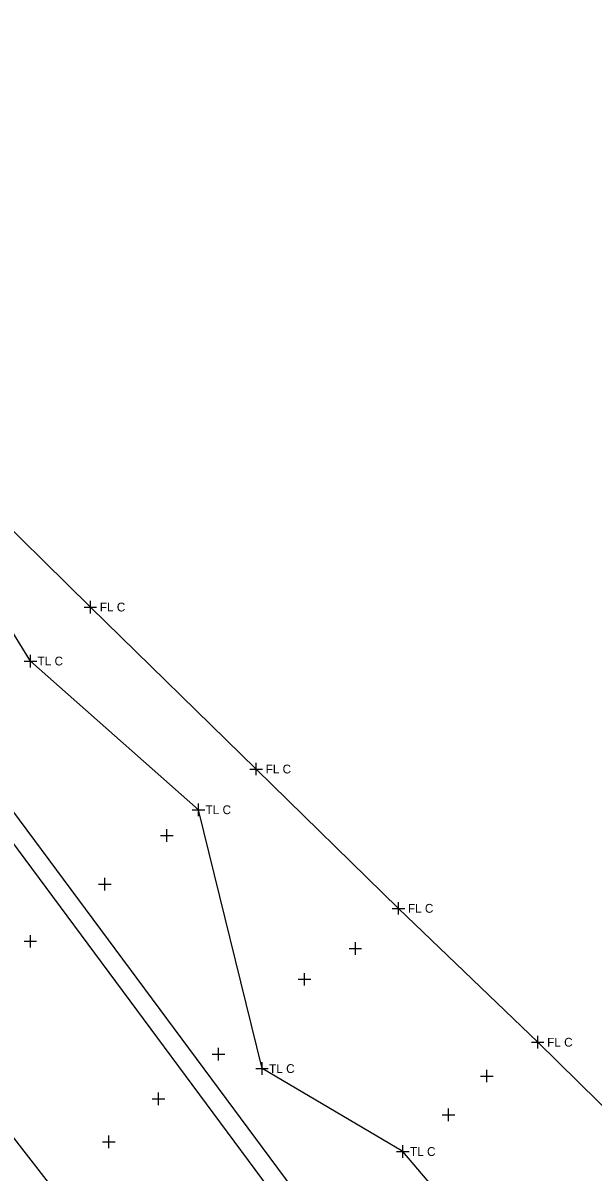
# Model space of a CAD drawing. Extents: x 1324236 to 1326110, y 459090 to 460782.
# Drawn here: x 1325707.2 to 1325797.9, y 459875.9 to 460058.5 of the extents above; entities that cross this region are included whole.
import ezdxf

# ---------------------------------------------------------------- set-up
doc = ezdxf.new("R2010")
doc.units = 0
for name, color, linetype in [('PM_X_CL_Double_Solid', 7, 'Continuous'), ('PV_X_Shoulder_Aggregate', 7, 'Continuous'), ('RD_X_GR_Lt', 7, 'Continuous'), ('RW_X_CL', 7, 'Continuous'), ('RW_X_Esmt_SH', 7, 'Continuous'), ('VG_X_Flower_Bed', 7, 'Continuous')]:
    doc.layers.add(name, color=color, linetype=linetype)

msp = doc.modelspace()

# ---------------------------------------------------------------- linework, layer by layer
at = {"layer": 'PM_X_CL_Double_Solid'}
for p, q in [((1325696.04, 459987.2), (1325717.94, 459965.66)), ((1325717.94, 459965.66), (1325744.3, 459939.92)), ((1325744.3, 459939.92), (1325766.92, 459917.78)), ((1325766.92, 459917.78), (1325789.06, 459896.5)), ((1325789.06, 459896.5), (1325812.12, 459873.88))]:
    msp.add_line(p, q, dxfattribs=at)
at = {"layer": 'PV_X_Shoulder_Aggregate'}
msp.add_lwpolyline([(1325606.5, 460003.97), (1325627.86, 459979.71), (1325648.47, 459953.75), (1325670.82, 459926.9), (1325690.92, 459900.29), (1325711.62, 459873.72), (1325733.33, 459849.01), (1325756.75, 459825.62), (1325779.78, 459800.49), (1325802.43, 459775.88), (1325825.37, 459750.4), (1325848.07, 459724.61), (1325869.88, 459700.51), (1325892.16, 459676.27), (1325913.97, 459651.72)], dxfattribs=at)
at = {"layer": 'RD_X_GR_Lt'}
for p, q in [((1325708.41, 459957.08), (1325689.63, 459987.5)), ((1325735.13, 459933.45), (1325708.41, 459957.08)), ((1325745.23, 459892.31), (1325735.13, 459933.45)), ((1325767.63, 459879.13), (1325745.23, 459892.31)), ((1325789.25, 459853.71), (1325767.63, 459879.13))]:
    msp.add_line(p, q, dxfattribs=at)
at = {"layer": 'RW_X_CL'}
for p, q in [((1325729.11, 459929.37), (1325731.11, 459929.37)), ((1325730.11, 459928.37), (1325730.11, 459930.37)), ((1325720.23, 459920.61), (1325720.23, 459922.61)), ((1325719.23, 459921.61), (1325721.23, 459921.61)), ((1325708.4, 459911.54), (1325708.4, 459913.54)), ((1325707.4, 459912.54), (1325709.4, 459912.54)), ((1325759.07, 459911.4), (1325761.07, 459911.4)), ((1325760.07, 459910.4), (1325760.07, 459912.4)), ((1325751.99, 459905.5), (1325751.99, 459907.5)), ((1325750.99, 459906.5), (1325752.99, 459906.5)), ((1325738.33, 459893.6), (1325738.33, 459895.6)), ((1325737.33, 459894.6), (1325739.33, 459894.6)), ((1325779.99, 459891.13), (1325781.99, 459891.13)), ((1325780.99, 459890.13), (1325780.99, 459892.13)), ((1325727.77, 459887.52), (1325729.77, 459887.52)), ((1325728.77, 459886.52), (1325728.77, 459888.52)), ((1325774.86, 459883.95), (1325774.86, 459885.95)), ((1325773.86, 459884.95), (1325775.86, 459884.95)), ((1325719.86, 459880.69), (1325721.86, 459880.69)), ((1325720.86, 459879.69), (1325720.86, 459881.69))]:
    msp.add_line(p, q, dxfattribs=at)
at = {"layer": 'RW_X_Esmt_SH'}
for p, q in [((1325717.94, 459964.66), (1325717.94, 459966.66)), ((1325716.94, 459965.66), (1325718.94, 459965.66)), ((1325707.41, 459957.08), (1325709.41, 459957.08)), ((1325708.41, 459956.08), (1325708.41, 459958.08)), ((1325744.3, 459938.92), (1325744.3, 459940.92)), ((1325743.3, 459939.92), (1325745.3, 459939.92)), ((1325734.13, 459933.45), (1325736.13, 459933.45)), ((1325735.13, 459932.45), (1325735.13, 459934.45)), ((1325766.92, 459916.78), (1325766.92, 459918.78)), ((1325765.92, 459917.78), (1325767.92, 459917.78)), ((1325788.06, 459896.5), (1325790.06, 459896.5)), ((1325789.06, 459895.5), (1325789.06, 459897.5)), ((1325745.23, 459891.31), (1325745.23, 459893.31)), ((1325744.23, 459892.31), (1325746.23, 459892.31)), ((1325767.63, 459878.13), (1325767.63, 459880.13)), ((1325766.63, 459879.13), (1325768.63, 459879.13))]:
    msp.add_line(p, q, dxfattribs=at)
at = {"layer": 'VG_X_Flower_Bed'}
for p, q in [((1325793.64, 459814.67), (1325591.57, 460086.9)), ((1325791.23, 459812.88), (1325589.16, 460085.11))]:
    msp.add_line(p, q, dxfattribs=at)

# ---------------------------------------------------------------- texts
at = {"layer": 'RW_X_Esmt_SH'}
for s, p in [('FL C', (1325719.44, 459964.96)), ('TL C', (1325709.54, 459956.38)), ('FL C', (1325745.8, 459939.22)), ('TL C', (1325736.25, 459932.75)), ('FL C', (1325768.42, 459917.08)), ('FL C', (1325790.56, 459895.8)), ('TL C', (1325746.36, 459891.61)), ('TL C', (1325768.76, 459878.43))]:
    msp.add_text(s, height=1.4, dxfattribs=at).set_placement(p)

doc.saveas('drawing.dxf')
